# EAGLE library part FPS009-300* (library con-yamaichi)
SD Card and MMC Reader (Manual Insertion) Source: http://www.yamaichi.de/pdf/c_fps009_3000.pdf
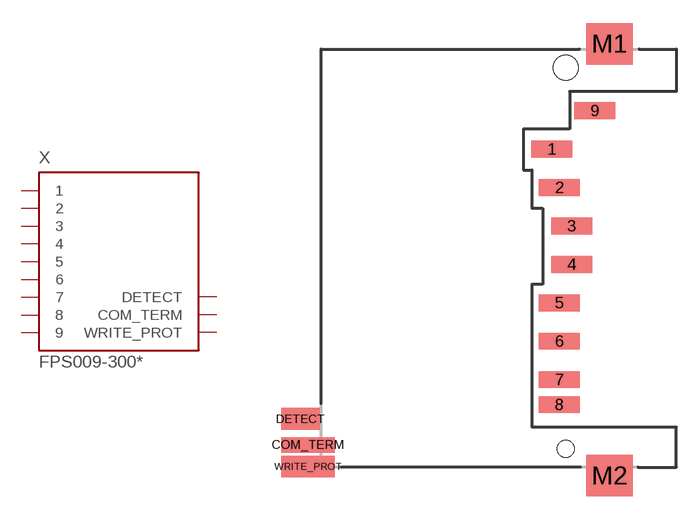
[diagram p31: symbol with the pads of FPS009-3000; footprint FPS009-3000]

Designator prefix X

## FPS009-3000 (OC_FARNELL: unknown; OC_NEWARK: unknown), FPS009-3001 (MPN: FPS009-3001-BL; OC_FARNELL: 1143952; OC_NEWARK: 91K9875), FPS009-3002 (OC_FARNELL: unknown; OC_NEWARK: unknown)  [FPS009-3000]
1  1  in
2  2  in
3  3  in
4  4  in
5  5  in
6  6  in
7  7  in
8  8  in
9  9  in
COM_TERM  COM_TERM  in
DETECT  DETECT  in
WRITE_PROT  WRITE_PROT  in

## Footprint FPS009-3000 (pad centres in mm)
SD Card and MMC Reader (Manual Insertion) Source: http://www.yamaichi.de/pdf/c_fps009_3000.pdf
smd 2.65 x 1.1: 1 -0.915,-5.3; 2 -0.415,-7.8; 3 0.385,-10.3; 4 0.385,-12.8; 5 -0.415,-15.3; 6 -0.415,-17.8; 7 -0.415,-20.3; 8 -0.415,-21.925; 9 1.885,-2.8
smd 3.5 x 1: COM_TERM -16.75,-24.55
smd 2.5 x 1.4: DETECT -17.25,-22.85
smd 3 x 2.7: M1 2.85,1.55; M2 2.85,-26.55
smd 3.5 x 1.4: WRITE_PROT -16.75,-25.95
hole 1.6 at 0,0
hole 1.1 at 0,-24.8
